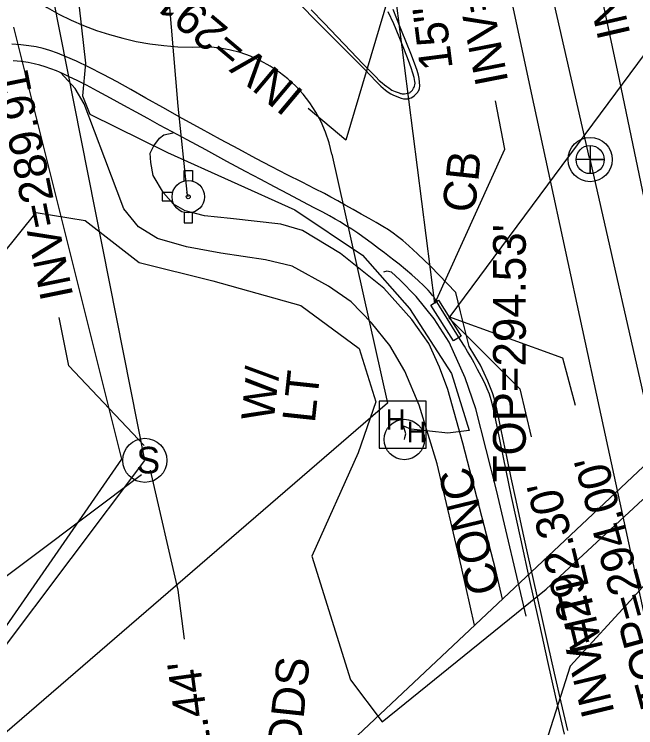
# Model space of a CAD drawing. Extents: x 2100323 to 2109811, y 740376 to 749755.
# Drawn here: x 2105884.5 to 2105960.4, y 740959.3 to 741046.3 of the extents above; entities that cross this region are included whole.
import ezdxf

# ---------------------------------------------------------------- set-up
doc = ezdxf.new("R2010")
doc.units = 0
for name, color, linetype in [('Exist Guardrail', 7, 'Continuous'), ('Exist Guardrail Text', 7, 'Continuous'), ('Exist Right of Way Easement Line', 7, 'Continuous'), ('Exist Right of Way Line', 7, 'Continuous'), ('Exist Roads Curbs', 7, 'Continuous'), ('Exist Roads EOP', 7, 'Continuous'), ('Exist Roads EOP Other', 7, 'Continuous'), ('Exist Roads EOP Other Text', 7, 'Continuous'), ('Exist Roads EOT', 7, 'Continuous'), ('Exist Structure Major Deck Tunnel Box Culvert', 7, 'Continuous'), ('Exist Structure Minor Catch Basin', 7, 'Continuous'), ('Exist Structure Minor Catch Basin Text', 7, 'Continuous'), ('Exist Structure Minor Catch Basin Top Elevation', 7, 'Continuous'), ('Exist Structure Minor Pipes RCP 15 Inch', 7, 'Continuous'), ('Exist Structure Minor Pipes RCP 15 Inch Invert', 7, 'Continuous'), ('Exist Structure Minor Pipes RCP 15 Inch Leader', 7, 'Continuous'), ('Exist Structure Minor Pipes RCP 15 Inch Text', 7, 'Continuous'), ('Exist Structure Minor Pipes RCP 36 Inch', 7, 'Continuous'), ('Exist Structure Minor Pipes RCP 36 Inch Invert', 7, 'Continuous'), ('Exist Structure Minor Pipes RCP 36 Inch Leader', 7, 'Continuous'), ('Exist Structure Minor Storm Sewer Manhole CELL', 7, 'Continuous'), ('Exist Structure Minor Storm Sewer Manhole Leader', 7, 'Continuous'), ('Exist Structure Minor Storm Sewer Manhole Text', 7, 'Continuous'), ('Exist Utilities Other Pole CELL', 7, 'Continuous'), ('Exist Utilities Other Pole Text', 7, 'Continuous'), ('Exist Utilities Power Hand Hole CELL', 7, 'Continuous'), ('Exist Utilities Power UG Cable SUE LOS B', 7, 'Continuous'), ('Exist Utilities Sanitary Sewer Manhole CELL', 7, 'Continuous'), ('Exist Utilities Sanitary Sewer Manhole Text', 7, 'Continuous'), ('Exist Utilities Sanitary Sewer UG Line', 7, 'Continuous'), ('Exist Utilities Sanitary Sewer UG Line Invert Elevation', 7, 'Continuous'), ('Exist Utilities Water Fire Hydrant CELL', 7, 'Continuous'), ('Exist Utilities Water UG Line SUE LOS B', 7, 'Continuous'), ('Exist Vegetation Woods Line', 7, 'Continuous'), ('Exist Vegetation Woods Line Text', 7, 'Continuous')]:
    doc.layers.add(name, color=color, linetype=linetype)

msp = doc.modelspace()

# ---------------------------------------------------------------- linework, layer by layer
at = {"layer": 'Exist Guardrail'}
msp.add_lwpolyline([(2105947.012, 740972.895), (2105943.362, 740988.273), (2105940.835, 740998.184), (2105939.548, 741001.988), (2105937.603, 741006.335), (2105935.77, 741009.188), (2105933.554, 741011.904), (2105931.565, 741013.94), (2105930.542, 741014.878), (2105929.977, 741015.01), (2105929.572, 741014.873)], dxfattribs=at)
at = {"layer": 'Exist Right of Way Easement Line'}
for p, q in [((2105897.655, 740992.059), (2105884.468, 741044.785)), ((2105829.718, 740894.066), (2105897.655, 740992.059))]:
    msp.add_line(p, q, dxfattribs=at)
at = {"layer": 'Exist Right of Way Line'}
for p, q in [((2105923.287, 741029.279), (2105930.088, 740998.881)), ((2105930.088, 740998.881), (2105870.378, 740947.413))]:
    msp.add_line(p, q, dxfattribs=at)
for centre, radius, start, end in [((2105906.559, 741078.382), 36.06, 186.67844, 272.28061), ((2105907.352, 741026.117), 16.246, 11.22344, 87.73561)]:
    msp.add_arc(centre, radius, start, end, dxfattribs=at)
at = {"layer": 'Exist Roads Curbs'}
for points in [[(2105920.762, 741046.866), (2105922.344, 741045.237), (2105923.936, 741043.584), (2105925.602, 741041.835), (2105927.069, 741040.295), (2105928.063, 741039.264), (2105928.633, 741038.692), (2105929.069, 741038.275), (2105929.418, 741037.962), (2105929.712, 741037.719), (2105929.982, 741037.516), (2105930.226, 741037.35), (2105930.437, 741037.21), (2105930.613, 741037.095), (2105930.791, 741036.995), (2105931.008, 741036.901), (2105931.256, 741036.815), (2105931.478, 741036.741), (2105931.666, 741036.68), (2105931.753, 741036.657), (2105931.844, 741036.643), (2105931.938, 741036.637), (2105932.137, 741036.651), (2105932.333, 741036.681), (2105932.51, 741036.709), (2105932.668, 741036.741), (2105932.744, 741036.771), (2105932.82, 741036.812), (2105932.894, 741036.865), (2105932.968, 741036.929), (2105933.112, 741037.094), (2105933.255, 741037.309), (2105933.326, 741037.436), (2105933.385, 741037.58), (2105933.42, 741037.745), (2105933.432, 741037.93), (2105933.42, 741038.137), (2105933.33, 741038.612), (2105933.176, 741039.169), (2105932.963, 741039.805), (2105932.635, 741040.682), (2105932.14, 741041.961), (2105931.497, 741043.577), (2105930.833, 741045.155), (2105930.17, 741046.631)], [(2105951.663, 740958.52), (2105950.636, 740963.022), (2105949.655, 740967.354), (2105948.644, 740971.863), (2105947.527, 740976.897), (2105946.332, 740982.341), (2105945.224, 740987.501), (2105944.23, 740992.262), (2105943.442, 740996.064), (2105942.955, 740998.346), (2105942.726, 740999.293), (2105942.506, 741000.001), (2105942.253, 741000.652), (2105941.941, 741001.331), (2105941.543, 741002.122), (2105941.075, 741003), (2105940.633, 741003.811), (2105940.233, 741004.53), (2105939.849, 741005.195), (2105939.457, 741005.846), (2105939.022, 741006.542), (2105938.332, 741007.648), (2105937.352, 741009.224), (2105936.425, 741010.714), (2105935.895, 741011.563), (2105935.708, 741011.854), (2105935.54, 741012.085), (2105935.336, 741012.339), (2105935.018, 741012.687), (2105934.505, 741013.2), (2105933.815, 741013.857), (2105933.06, 741014.536), (2105932.258, 741015.215), (2105931.496, 741015.835), (2105930.859, 741016.338), (2105930.32, 741016.749), (2105929.702, 741017.22), (2105928.976, 741017.777), (2105928.248, 741018.331), (2105927.621, 741018.794), (2105927.07, 741019.184), (2105926.439, 741019.614), (2105925.702, 741020.101), (2105924.952, 741020.583), (2105924.281, 741020.997), (2105923.667, 741021.358), (2105922.971, 741021.748), (2105922.168, 741022.181), (2105921.127, 741022.732), (2105919.716, 741023.474), (2105917.987, 741024.38), (2105916.263, 741025.287), (2105914.597, 741026.167), (2105912.748, 741027.153), (2105910.472, 741028.379), (2105907.879, 741029.784), (2105905.621, 741031.007), (2105903.805, 741031.988), (2105902.256, 741032.824), (2105900.797, 741033.615), (2105899.4, 741034.375), (2105897.899, 741035.2), (2105896.264, 741036.106), (2105894.678, 741036.974), (2105893.324, 741037.685), (2105892.191, 741038.247), (2105891.223, 741038.716), (2105890.411, 741039.101), (2105889.688, 741039.42), (2105888.983, 741039.69), (2105888.297, 741039.915), (2105887.623, 741040.115), (2105886.958, 741040.294), (2105886.229, 741040.446), (2105885.36, 741040.562), (2105884.364, 741040.64)]]:
    msp.add_lwpolyline(points, dxfattribs=at)
at = {"layer": 'Exist Roads EOP'}
for points in [[(2105917.019, 741049.977), (2105923.842, 741043.067), (2105927.286, 741039.584), (2105928.649, 741038.196), (2105928.961, 741037.871), (2105929.252, 741037.576), (2105929.528, 741037.309), (2105929.829, 741037.061), (2105930.159, 741036.828), (2105930.495, 741036.625), (2105930.813, 741036.463), (2105931.114, 741036.338), (2105931.416, 741036.224), (2105931.72, 741036.116), (2105932.018, 741036.039), (2105932.16, 741036.02), (2105932.298, 741036.014), (2105932.559, 741036.037), (2105932.785, 741036.086), (2105932.974, 741036.156), (2105933.157, 741036.263), (2105933.364, 741036.425), (2105933.586, 741036.633), (2105933.763, 741036.839), (2105933.831, 741036.939), (2105933.886, 741037.036), (2105933.928, 741037.144), (2105933.962, 741037.278), (2105933.998, 741037.621), (2105933.994, 741038.051), (2105933.948, 741038.488), (2105933.857, 741038.917), (2105933.675, 741039.493), (2105933.354, 741040.373), (2105932.903, 741041.537), (2105932.38, 741042.87), (2105931.794, 741044.354), (2105931.225, 741045.773), (2105930.751, 741046.912)], [(2105952.078, 740958.951), (2105951.277, 740962.407), (2105950.466, 740965.941), (2105949.647, 740969.552), (2105948.819, 740973.238), (2105947.983, 740976.998), (2105947.176, 740980.639), (2105946.437, 740983.97), (2105945.766, 740987), (2105945.162, 740989.796), (2105944.624, 740992.369), (2105944.154, 740994.659), (2105943.75, 740996.608), (2105943.411, 740998.206), (2105943.128, 740999.389), (2105942.898, 741000.148), (2105942.648, 741000.781), (2105942.305, 741001.585), (2105941.877, 741002.539), (2105941.412, 741003.508), (2105940.056, 741005.819), (2105938.969, 741010.024), (2105938.406, 741012.382), (2105935.318, 741015.625), (2105933.746, 741017.102), (2105932.679, 741018.078), (2105931.928, 741018.731), (2105931.302, 741019.243), (2105930.776, 741019.634), (2105930.18, 741020.031), (2105929.488, 741020.455), (2105928.701, 741020.916), (2105927.823, 741021.423), (2105926.864, 741021.969), (2105925.893, 741022.516), (2105924.921, 741023.058), (2105923.995, 741023.571), (2105923.165, 741024.028), (2105922.366, 741024.461), (2105921.212, 741025.055), (2105919.64, 741025.84), (2105917.828, 741026.75), (2105915.955, 741027.716), (2105914.008, 741028.744), (2105911.918, 741029.861), (2105909.672, 741031.071), (2105907.341, 741032.342), (2105904.993, 741033.64), (2105902.665, 741034.944), (2105900.575, 741036.122), (2105898.759, 741037.151), (2105897.068, 741038.092), (2105895.348, 741039.006), (2105893.635, 741039.876), (2105892.127, 741040.598), (2105890.857, 741041.153), (2105889.78, 741041.58), (2105888.85, 741041.918), (2105888.041, 741042.169), (2105887.199, 741042.36), (2105886.3, 741042.494), (2105885.315, 741042.597), (2105884.214, 741042.695)]]:
    msp.add_lwpolyline(points, dxfattribs=at)
at = {"layer": 'Exist Roads EOP Other'}
for points in [[(2105940.708, 740971.791), (2105939.116, 740978.874), (2105936.138, 740991.504), (2105933.924, 740998.631), (2105932.188, 741002.796), (2105930.336, 741005.94), (2105928.11, 741008.69), (2105925.633, 741011.25), (2105922.852, 741013.155), (2105918.445, 741015.592), (2105915.18, 741016.373), (2105909.714, 741017.21), (2105905.532, 741017.982), (2105901.988, 741018.974), (2105899.681, 741020.409), (2105897.892, 741022.606), (2105895.556, 741028.733), (2105893.062, 741035.401), (2105891.958, 741037.292), (2105890.197, 741039.207)], [(2105944.093, 740974.974), (2105943.288, 740978.478), (2105939.258, 740994.005), (2105937.428, 741000.552), (2105936.424, 741003.287), (2105935.13, 741006.184), (2105933.034, 741009.115), (2105929.605, 741012.941), (2105924.342, 741017.147), (2105919.684, 741019.948), (2105917.068, 741020.738), (2105910.89, 741021.414), (2105907.749, 741021.764), (2105905.369, 741022.362), (2105903.956, 741023.169), (2105902.747, 741024.558), (2105901.485, 741026.683), (2105901.167, 741028.244), (2105901.119, 741029.404), (2105901.553, 741030.304), (2105902.238, 741031.214), (2105902.788, 741031.637), (2105903.91, 741031.859)]]:
    msp.add_lwpolyline(points, dxfattribs=at)
at = {"layer": 'Exist Roads EOT'}
for points in [[(2105890.846, 741349.335), (2105899.432, 741309.704), (2105908.147, 741270.242), (2105916.616, 741231.659), (2105925.02, 741193.008), (2105933.585, 741153.59), (2105941.665, 741116.136), (2105950.104, 741077.074), (2105958.397, 741038.167), (2105966.547, 740998.978), (2105974.788, 740961.942), (2105983.851, 740922.306), (2105991.887, 740882.238), (2105995.873, 740842.797), (2105992.71, 740801.767), (2105978.277, 740756.909), (2105971.197, 740741.935), (2105964.095, 740728.984), (2105953.18, 740711.232), (2105942.499, 740696.213), (2105929.601, 740680.649), (2105916.153, 740666.014), (2105888.786, 740636.954), (2105887.605, 740635.562)], [(2105884.458, 741327.17), (2105889.032, 741306.325), (2105897.404, 741268.101), (2105905.961, 741229.52), (2105914.206, 741191.35), (2105922.67, 741151.86), (2105931.018, 741113.223), (2105939.342, 741075.347), (2105947.597, 741036.734), (2105955.91, 740998.365), (2105964.546, 740958.588)]]:
    msp.add_lwpolyline(points, dxfattribs=at)
at = {"layer": 'Exist Structure Major Deck Tunnel Box Culvert'}
msp.add_lwpolyline([(2106055.634, 740987.34), (2105937.68, 740881.899), (2105922.326, 740954.512), (2105967.458, 740996.938), (2106021.602, 741044.192)], dxfattribs=at)
at = {"layer": 'Exist Structure Minor Catch Basin'}
msp.add_lwpolyline([(2105936.291, 741011.442), (2105939.062, 741007.079), (2105938.135, 741006.49), (2105935.365, 741010.853)], close=True, dxfattribs=at)
at = {"layer": 'Exist Structure Minor Catch Basin Top Elevation'}
msp.add_lwpolyline([(2105937.525, 741009.46), (2105951.412, 741004.426), (2105952.987, 740998.636)], dxfattribs=at)
at = {"layer": 'Exist Structure Minor Pipes RCP 15 Inch'}
for p, q in [((2105975.486, 741060.438), (2105937.571, 741009.301)), ((2105935.846, 741011.046), (2105930.755, 741051.036))]:
    msp.add_line(p, q, dxfattribs=at)
at = {"layer": 'Exist Structure Minor Pipes RCP 15 Inch Leader'}
for points in [[(2105930.66, 741050.016), (2105924.993, 741030.989), (2105920.401, 741034.85)], [(2105935.846, 741011.046), (2105944.405, 741029.871), (2105943.254, 741035.76)], [(2105937.571, 741009.301), (2105946.206, 741000.628), (2105947.615, 740994.796)]]:
    msp.add_lwpolyline(points, dxfattribs=at)
at = {"layer": 'Exist Structure Minor Pipes RCP 36 Inch'}
for p, q in [((2105900.453, 740991.936), (2105818.937, 741403.317)), ((2105826.584, 740893.842), (2105900.45, 740991.901))]:
    msp.add_line(p, q, dxfattribs=at)
at = {"layer": 'Exist Structure Minor Pipes RCP 36 Inch Leader'}
for points in [[(2105900.373, 740993.746), (2105891.188, 741003.443), (2105889.992, 741009.323)], [(2105900.054, 740990.146), (2105873.328, 740970.082), (2105872.027, 740975.94)]]:
    msp.add_lwpolyline(points, dxfattribs=at)
at = {"layer": 'Exist Structure Minor Storm Sewer Manhole CELL'}
msp.add_circle((2105900.455, 740991.915), 2.694, dxfattribs=at)
at = {"layer": 'Exist Structure Minor Storm Sewer Manhole Leader'}
msp.add_lwpolyline([(2105901.111, 740990.707), (2105904.461, 740976.06), (2105905.264, 740970.114)], dxfattribs=at)
at = {"layer": 'Exist Utilities Other Pole CELL'}
msp.add_circle((2105932.13, 740994.461), 2.463, dxfattribs=at)
at = {"layer": 'Exist Utilities Power Hand Hole CELL'}
msp.add_line((2105932.005, 740996.126), (2105932.005, 740996.126), dxfattribs=at)
msp.add_lwpolyline([(2105929.055, 740993.401), (2105934.805, 740993.401), (2105934.805, 740999.151), (2105929.055, 740999.151), (2105929.055, 740993.401)], dxfattribs=at)
at = {"layer": 'Exist Utilities Power UG Cable SUE LOS B'}
for p, q in [((2105932.184, 740994.696), (2105932.298, 740995.148)), ((2105932.13, 740994.463), (2105932.184, 740994.696))]:
    msp.add_line(p, q, dxfattribs=at)
for points in [[(2105893.366, 741135.162), (2105894.332, 741122.04), (2105893.906, 741110.868), (2105892.532, 741102.098), (2105890.966, 741086.7), (2105888.839, 741074.988), (2105891.194, 741058.378), (2105893.2, 741040.359), (2105892.859, 741036.391), (2105893.725, 741034.145), (2105903.214, 741029.46), (2105918.743, 741022.486), (2105927.032, 741016.943), (2105932.771, 741010.439), (2105937.884, 741002.5), (2105940.019, 740995.564), (2105937.446, 740995.245), (2105932.958, 740995.705)], [(2105932.298, 740995.148), (2105932.004, 740996.126), (2105932.958, 740995.705)]]:
    msp.add_lwpolyline(points, dxfattribs=at)
at = {"layer": 'Exist Utilities Sanitary Sewer Manhole CELL'}
msp.add_lwpolyline([(2105954.799, 741030.321), (2105954.799, 741026.896), (2105954.799, 741028.609), (2105956.512, 741028.609), (2105953.087, 741028.609)], dxfattribs=at)
for radius in [2.694, 1.712]:
    msp.add_circle((2105954.799, 741028.609), radius, dxfattribs=at)
at = {"layer": 'Exist Utilities Sanitary Sewer UG Line'}
for p, q in [((2105954.722, 741028.764), (2105904.664, 741248.565)), ((2106015.589, 740759.993), (2105954.862, 741028.478))]:
    msp.add_line(p, q, dxfattribs=at)
at = {"layer": 'Exist Utilities Water Fire Hydrant CELL'}
msp.add_line((2105905.751, 741024.076), (2105905.751, 741024.076), dxfattribs=at)
for points in [[(2105905.239, 741025.988), (2105905.239, 741027.276), (2105906.264, 741027.276), (2105906.264, 741025.963)], [(2105903.839, 741024.588), (2105902.551, 741024.588), (2105902.551, 741023.563), (2105903.839, 741023.563)], [(2105905.239, 741022.163), (2105905.239, 741020.876), (2105906.264, 741020.876), (2105906.264, 741022.188)]]:
    msp.add_lwpolyline(points, dxfattribs=at)
for radius in [1.977, 0.243]:
    msp.add_circle((2105905.751, 741024.076), radius, dxfattribs=at)
at = {"layer": 'Exist Utilities Water UG Line SUE LOS B'}
msp.add_line((2105905.751, 741024.076), (2105905.575, 741024.639), dxfattribs=at)
msp.add_lwpolyline([(2105813.254, 741516.95), (2105813.412, 741515.53), (2105826.011, 741437.296), (2105843.724, 741349.871), (2105874.852, 741202.77), (2105896.784, 741084.661), (2105901.965, 741063.762), (2105900.509, 741063.329), (2105902.846, 741054.438), (2105904.488, 741035.146), (2105905.575, 741024.639)], dxfattribs=at)
at = {"layer": 'Exist Vegetation Woods Line'}
msp.add_lwpolyline([(2105857.476, 740948.979), (2105862.576, 740960.588), (2105866.48, 740972.646), (2105870.359, 740989.37), (2105877.404, 741006.042), (2105883.057, 741016.989), (2105887.201, 741022.159), (2105893.161, 741021.188), (2105899.739, 741016.062), (2105908.756, 741013.823), (2105919.474, 741010.794), (2105926.611, 741005.541), (2105928.648, 740999.053), (2105926.474, 740992.814), (2105920.823, 740980.212), (2105925.542, 740965.139), (2105929.425, 740960.003), (2105949.432, 740976.218), (2105961.238, 740987.147), (2105966.479, 740988.785), (2105968.701, 740984.805), (2105960.136, 740975.279), (2105952.365, 740966.809), (2105949.094, 740956.6)], dxfattribs=at)

# ---------------------------------------------------------------- texts
at = {"layer": 'Exist Guardrail Text'}
msp.add_text('MTL', height=4, rotation=102.95729, dxfattribs=at).set_placement((2105956.432, 740968.935))
at = {"layer": 'Exist Roads EOP Other Text'}
msp.add_text('CONC', height=4, rotation=103.80649, dxfattribs=at).set_placement((2105943.889, 740976.069))
at = {"layer": 'Exist Structure Minor Catch Basin Text'}
msp.add_text('CB', height=4, rotation=83.88645, dxfattribs=at).set_placement((2105940.719, 741022.019))
at = {"layer": 'Exist Structure Minor Catch Basin Top Elevation'}
msp.add_text("TOP=294.00'", height=4, rotation=105.22385, dxfattribs=at).set_placement((2105964.904, 740962.465))
at = {"layer": 'Exist Structure Minor Pipes RCP 15 Inch Invert'}
for s, rotation, p in [("INV=292.62'", 101.05207, (2105944.834, 741038.106)), ("INV=291.39'", 139.94952, (2105920.036, 741036.805)), ("INV=292.30'", 103.57747, (2105957.807, 740961.113))]:
    msp.add_text(s, height=4, rotation=rotation, dxfattribs=at).set_placement(p)
at = {"layer": 'Exist Structure Minor Pipes RCP 15 Inch Text'}
msp.add_text('15" RCP', height=4, rotation=97.25535, dxfattribs=at).set_placement((2105938.05, 741039.766))
at = {"layer": 'Exist Structure Minor Pipes RCP 36 Inch Invert'}
msp.add_text("INV=289.91'", height=4, rotation=101.49685, dxfattribs=at).set_placement((2105891.738, 741011.947))
at = {"layer": 'Exist Structure Minor Storm Sewer Manhole CELL'}
msp.add_text('S', height=3.25, dxfattribs=at).set_placement((2105899.424, 740990.315))
at = {"layer": 'Exist Structure Minor Storm Sewer Manhole Text'}
msp.add_text("TOP=301.44'", height=4, rotation=97.68453, dxfattribs=at).set_placement((2105911.33, 740936.459))
at = {"layer": 'Exist Utilities Other Pole Text'}
for s, p in [('W/', (2105916.179, 740996.574)), ('LT', (2105921.196, 740996.386))]:
    msp.add_text(s, height=4, rotation=83.88645, dxfattribs=at).set_placement(p)
at = {"layer": 'Exist Utilities Power Hand Hole CELL'}
for p in [(2105929.846, 740995.652), (2105932.41, 740994.131)]:
    msp.add_text('H', height=2.5, dxfattribs=at).set_placement(p)
at = {"layer": 'Exist Utilities Sanitary Sewer Manhole Text'}
msp.add_text("TOP=294.53'", height=4, rotation=90, dxfattribs=at).set_placement((2105946.951, 740989.248))
at = {"layer": 'Exist Utilities Sanitary Sewer UG Line Invert Elevation'}
msp.add_text("INV=287.64'", height=4, rotation=102.98681, dxfattribs=at).set_placement((2105959.747, 741043.878))
at = {"layer": 'Exist Vegetation Woods Line Text'}
msp.add_text('WOODS', height=4, rotation=83.88645, dxfattribs=at).set_placement((2105918.386, 740947.027))

doc.saveas('drawing.dxf')
